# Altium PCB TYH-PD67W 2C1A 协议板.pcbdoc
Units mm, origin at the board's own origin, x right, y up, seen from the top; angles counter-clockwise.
Board outline 94.32 x 66.89 mm, 5 copper layers (Top Layer, Signal Layer 3, Signal Layer 1, Signal Layer 2, Bottom Layer), stack 0.941 mm thick; 46 components, 153 nets, 245 pads, 157 vias.
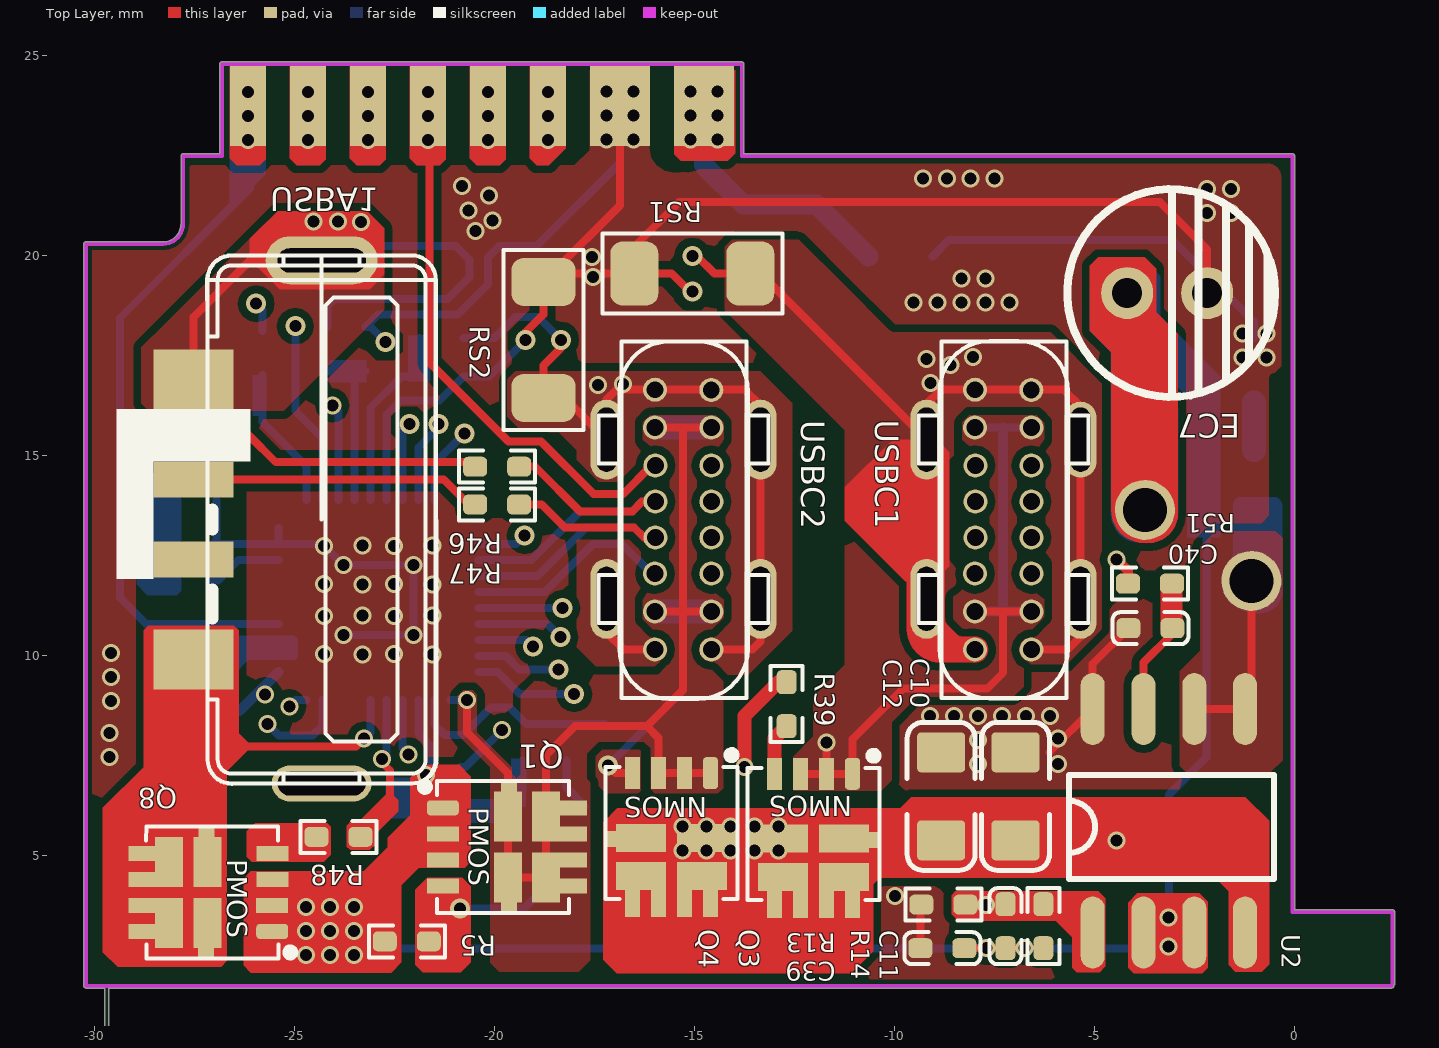
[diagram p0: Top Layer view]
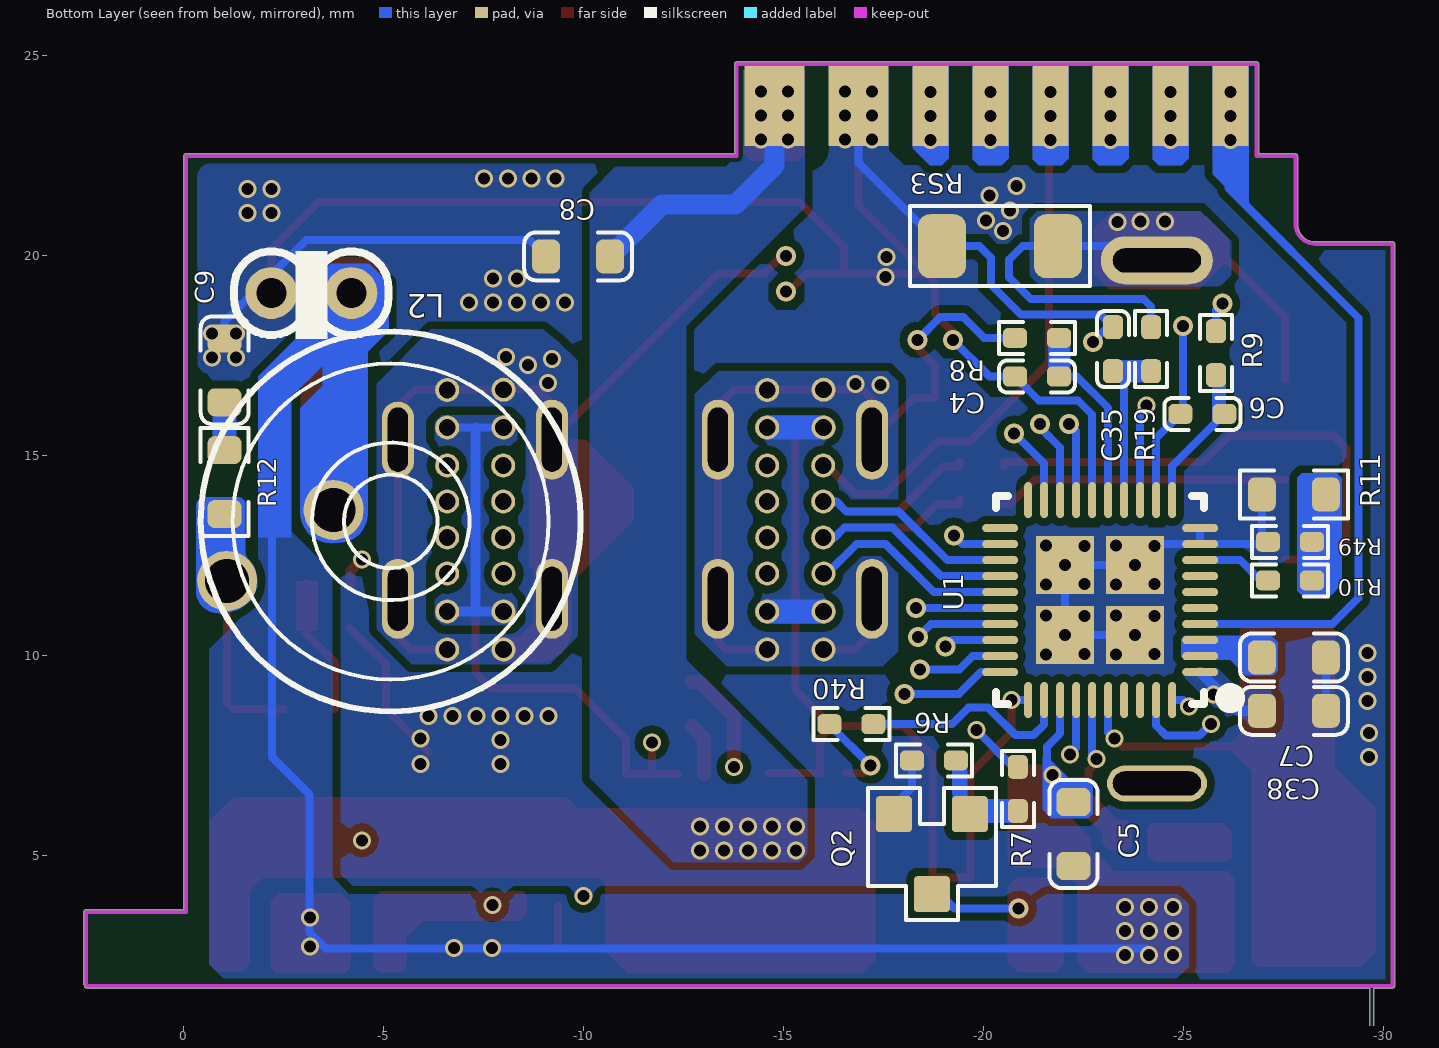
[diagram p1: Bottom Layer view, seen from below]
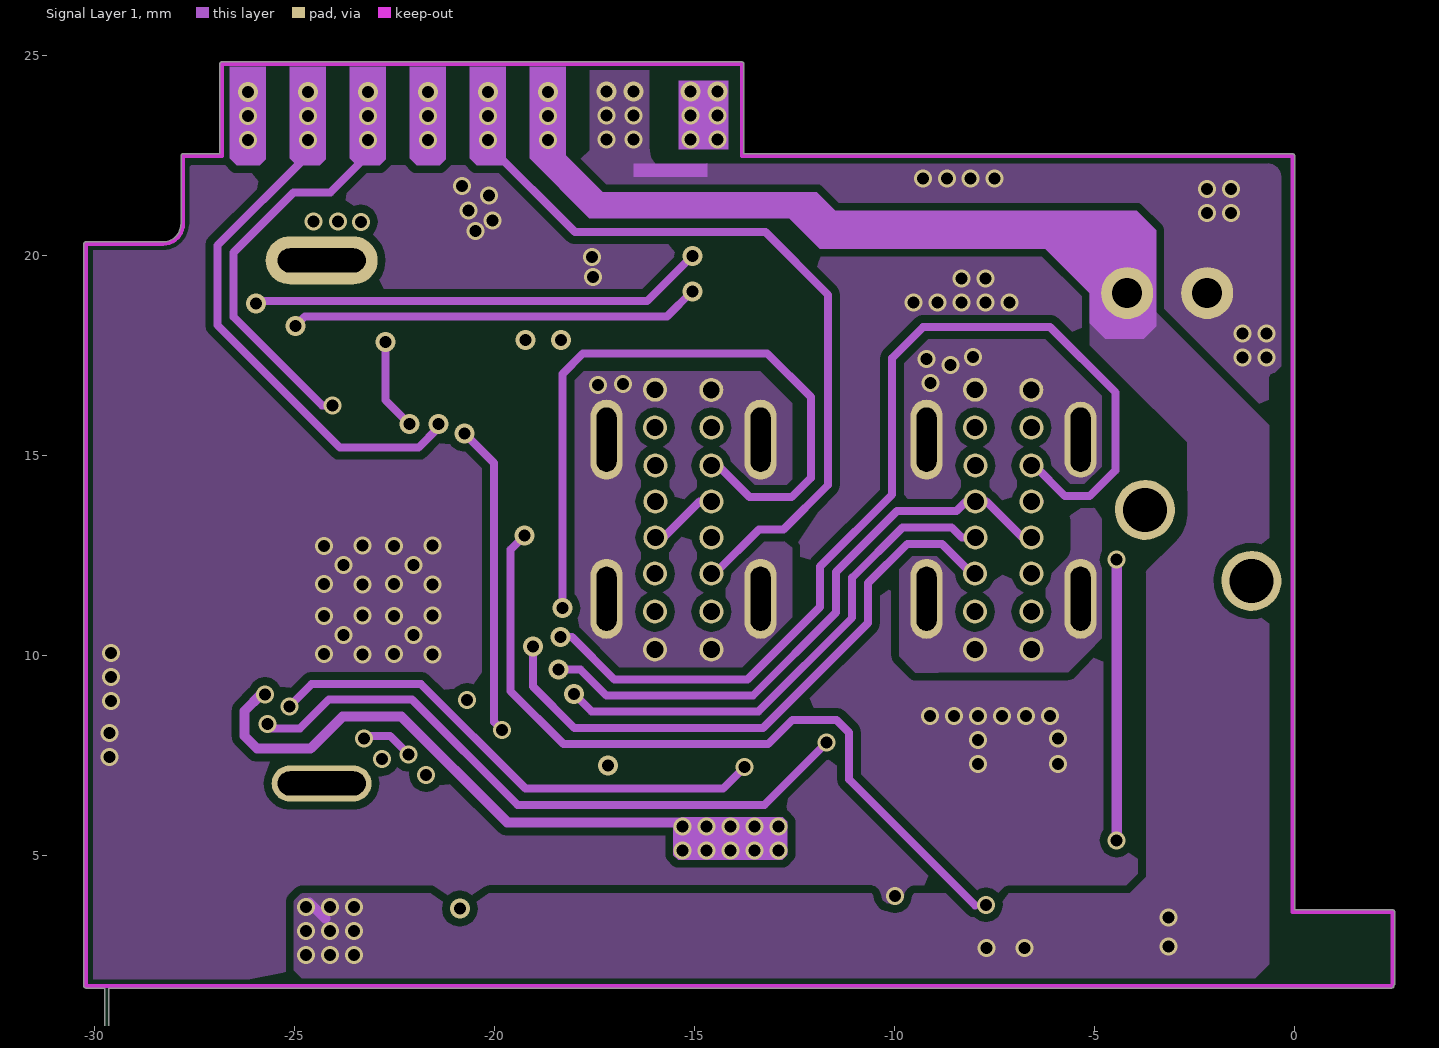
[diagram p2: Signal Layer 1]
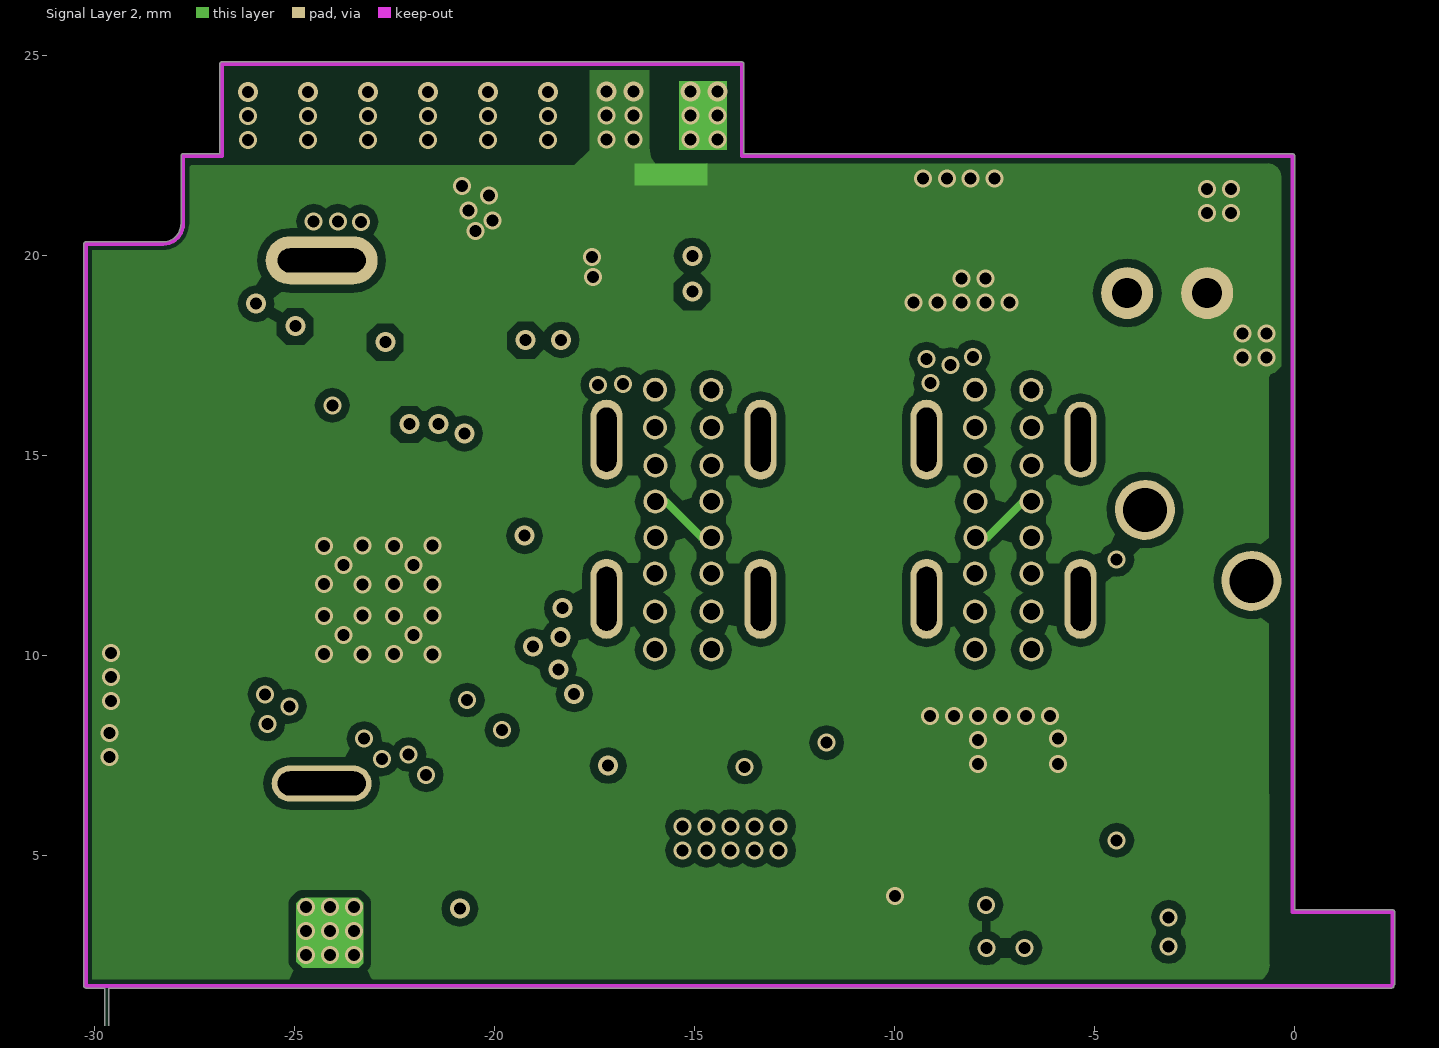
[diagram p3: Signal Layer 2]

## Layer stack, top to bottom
Top Solder: solder mask 0.0102, Solder Resist, Dk 3.5
Top Layer: signal copper 0.0356
Dielectric 1: core 0.254, FR-4, Dk 4.2
Signal Layer 3: signal copper 0.036
Dielectric 4: prepreg 0.127, Dk 4.2
Signal Layer 1: signal copper 0.036
Dielectric 2: core 0.254, Dk 4.2
Signal Layer 2: signal copper 0.036
Dielectric 3: prepreg 0.127, Dk 4.2
Bottom Layer: signal copper 0.0356
Bottom Solder: solder mask 0.0102, Solder Resist, Dk 3.5

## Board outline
-60.945,-41.225 -45.944,-41.225 ccw(c-45.944,-41.2) -45.919,-41.2 -45.919,-38.225 -43.445,-38.225 ccw(c-43.445,-38.2) -43.419,-38.2 -43.419,-37 ccw(c-43.445,-37) -43.445,-36.975 -45.919,-36.975 -45.919,-35.625 -43.445,-35.625 ccw(c-43.445,-35.6) -43.419,-35.6 -43.419,-34.4 ccw(c-43.445,-34.4) -43.445,-34.375 -45.919,-34.375 -45.919,-32.925 -43.445,-32.925 ccw(c-43.445,-32.9) -43.419,-32.9 -43.419,-27.85 -39.751,-27.85 -39.759,-40.693 ccw(c-39.709,-40.7) -39.709,-40.75 -29.759,-40.752 -29.76,-42.002 ccw(c-29.71,-42.002) -29.71,-42.052 0,-42.052 ccw(c0,-42.002) 0.05,-42.002 0.05,-37.55 2.5,-37.55 ccw(c2.5,-37.5) 2.55,-37.5 2.55,-32.55 5.163,-32.55 5.16,-37.409 ccw(c5.21,-37.409) 5.16,-37.409 ccw(c8.207,-37.409) 8.207,-40.456 ccw(c8.207,-40.406) 8.207,-40.456 ccw(c8.207,-40.406) 8.207,-40.456 25.296,-40.456 ccw(c25.296,-40.406) 25.308,-40.455 ccw(c25.296,-37.407) 28.344,-37.407 28.352,-4.393 ccw(c28.302,-4.393) 28.352,-4.393 ccw(c28.302,-4.393) 28.351,-4.381 ccw(c25.304,-4.393) 25.304,-1.346 8.229,-1.346 ccw(c8.229,-4.393) 5.181,-4.375 ccw(c5.228,-4.393) 5.178,-4.393 5.175,-9.653 ccw(c5.225,-9.653) 5.225,-9.703 6.674,-9.704 6.673,-10.703 5.225,-10.702 ccw(c5.225,-10.753) 5.174,-10.753 5.163,-32.45 0.05,-32.45 0.05,-9.32 2.5,-9.32 ccw(c2.5,-9.269) 2.55,-9.269 2.55,-2.769 ccw(c2.5,-2.769) 2.5,-2.719 0.05,-2.719 0.05,0 ccw(c0,0) 0,0.05 -29.65,0.05 -29.65,1.682 2.433,1.682 ccw(c2.433,1.733) 2.483,1.733 ccw(c2.433,1.733) 2.482,1.745 ccw(c2.45,1.784) 2.5,1.784 2.5,3.584 ccw(c2.45,3.584) 2.45,3.635 0,3.635 0,22.484 ccw(c-0.05,22.484) -0.014,22.52 ccw(c-0.05,22.484) -0.05,22.535 -13.768,22.535 -13.768,24.784 ccw(c-13.819,24.784) -13.819,24.835 -26.819,24.835 ccw(c-26.819,24.784) -26.869,24.784 -26.869,22.535 -27.789,22.535 ccw(c-27.789,22.484) -27.84,22.483 -27.84,20.784 cw(c-28.289,20.784) -28.289,20.335 cw(c-28.289,20.784) -28.289,20.335 cw(c-28.289,20.284) -28.289,20.335 -30.217,20.335 ccw(c-30.217,20.284) -30.268,20.284 -30.268,1.733 ccw(c-30.217,1.733) -30.217,1.682 -29.75,1.682 -29.75,-1.25 -31.7,-1.25 ccw(c-31.7,-1.3) -31.75,-1.3 -31.75,-26.75 -39.7,-26.75 ccw(c-39.7,-26.8) -39.75,-26.8 -39.751,-27.75 -43.445,-27.75 ccw(c-43.445,-27.8) -43.488,-27.775 -45.919,-27.775 -45.919,-24.3 ccw(c-45.945,-24.3) -45.945,-24.275 -65.945,-24.275 ccw(c-65.945,-24.3) -65.97,-24.3 -65.97,-36.2 ccw(c-60.945,-36.2)

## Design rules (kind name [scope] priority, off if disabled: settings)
Clearance Clearance_19 [InNet('NetC4_2') vs InNet('PGND')] p1: gap=0.4
Clearance Clearance_18 [InNet('NetR15_1') vs InNet('PGND')] p2: gap=1
Clearance Clearance_17 [InNet('NetN_1') vs InNet('NetBD1_1')] p3: gap=1.55
Clearance Clearance_16 [InNet('NetN_1') vs InNet('PGND')] p4: gap=1.5
Clearance Clearance_15 [InNet('VIN') vs InNet('PGND')] p5 off: gap=5.8
Clearance Clearance_14 [InNet('CS') vs InNet('Bais-L')] p6: gap=0.45
Clearance Clearance_13 [InNet('SW') vs InNet('CS')] p7: gap=1.5
Clearance Clearance_12 [InNet('NetR15_1') vs InNet('CS')] p8: gap=1
Clearance Clearance_11 [InNet('NetBD1_3') vs InNet('CS')] p9: gap=1.1
Clearance Clearance_10 [InNet('HV') vs InNet('CS')] p10: gap=1.1
Clearance Clearance_9 [InNet('NetL2_1') vs InNet('CS')] p11: gap=1.5
Clearance Clearance_8 [InNet('NetC1_2') vs InNet('PGND')] p12: gap=1.2
Clearance Clearance_7 [InNet('NetBD1_3') vs InNet('PGND')] p13: gap=1.2
Clearance Clearance_6 [InNet('NetC2_2') vs InNet('PGND')] p14: gap=1.3
Clearance Clearance_5 [InNet('Bais-L') vs InNet('PGND')] p15: gap=0.45
Clearance Clearance_4 [InNet('SW') vs InNet('PGND')] p16: gap=1.5
Clearance Clearance_3 [InNet('HV') vs InNet('PGND')] p17: gap=1.2
Clearance Clearance_2 [InNet('NetL2_1') vs InNet('PGND')] p18: gap=1.5
Clearance Clearance_1 [OnLayer('Keep-Out Layer')] p19: gap=0.1
Clearance [All] p20: gap=0.2
PlaneConnect [All] p1: planeconnectstyle=Direct reliefexpansion=0.508 reliefentries=4 reliefconductorwidth=0.3 reliefairgap=0.254
PolygonConnect [All] p1: connectstyle=Direct reliefconductorwidth=0.3 reliefentries=4 polygonreliefangle="90 Angle" airgapwidth=0.3
RoutingVias [All] p1: holewidth=0.711 width=1.27 viastyle="Through Hole" minholewidth=0.711 minwidth=1.27 maxholewidth=0.711 maxwidth=1.27
SolderMaskExpansion [All] p1: expansion=0.05
Width [All] p1: maxlimit=10 minlimit=0.1 preferedwidth=0.2
28 further rules are at their usual default settings.

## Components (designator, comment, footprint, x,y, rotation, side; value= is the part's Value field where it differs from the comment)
C4 "0.1uF" 0402C -22.279,16.568 r0 bottom
C5 "1uF" 0603CX -22.239,4.733 r90 bottom
C6 "0.1uF" 0402C -26.411,15.635 r0 bottom
C7 "1uF" 0603CX -26.947,9.945 r180 bottom
C8 "1uF" 0603CX -10.655,19.974 r0 bottom
C9 "100nF/50V/0603" 0603CX -1.018,17.925 r270 bottom
C10 "2.2nF/250V/0805" 0805C -6.977,6.474 r90 top
C11 "33nF/25V/0402" 0402C -6.826,4.177 r270 top (schematic designator C21)
C12 "100nF/50V/0603" 0805C -8.835,6.474 r90 top (schematic designator C9)
C35 "0.1uF" 0402C -22.826,16.704 r90 bottom
C38 "1uF" 0603CX -28.548,8.613 r0 bottom
C39 "33nF/25V/0402" 0402C -7.856,2.277 r180 top (schematic designator C21)
C40 "33nF/25V/0402" 0402C -4.555,11.078 r0 top (schematic designator C21)
EC7 "560uF/25V/6.3*16" EG-5*9L -4.184,19.056 r90 top (schematic designator EC6)
L2 "Comment" L-T31125W -5.169,13.346 r340 bottom
Q1 "PPM8PN03R10" DFN3*3 -18.718,5.974 r270 top
Q2 "2N7002KL SOT-23" SOT-23_R -18.699,5.028 r0 bottom (schematic designator Q8)
Q3 "PNM8PN30V50A" DFN3*3 -11.263,4.463 r180 top
Q4 "PNM8PN30V50A" DFN3*3 -14.814,4.479 r180 top
Q8 "PPM8PN03R10" DFN3*3 -28.135,3.309 r90 top
R5 "10K" 0402R#1 -22.746,2.848 r0 top (schematic designator R4)
R6 "10K" 0402R#1 -19.304,7.372 r0 bottom (schematic designator R4)
R7 "2K" 0402R#1 -20.847,7.21 r270 bottom (schematic designator R4)
R8 "100R" 0402R#1 -21.879,17.935 r0 bottom (schematic designator R4)
R9 "100R" 0402r -25.803,17.554 r270 bottom (schematic designator R4)
R10 "10K" 0402R#2 -27.654,11.872 r0 bottom (schematic designator R4)
R11 "100K" 0603Rx -26.947,14.024 r180 bottom (schematic designator R4)
R12 "10R/1206" 0603RX -1.018,15.132 r270 bottom (schematic designator R6)
R13 "1K/0402" 0402R#1 -8.231,3.767 r180 top (schematic designator R22)
R14 "1K/0402" 0402R#1 -6.281,2.677 r90 top (schematic designator R22)
R19 "100R" 0402R#1 -24.182,18.204 r270 bottom (schematic designator R4)
R39 "100R" 0402R#1 -12.698,8.229 r90 top (schematic designator R4)
R40 "100R" 0402R#1 -17.236,8.278 r0 bottom (schematic designator R4)
R46 "100R" 0402R#1 -19.386,14.714 r180 top (schematic designator R4)
R47 "100R" 0402R#1 -19.386,13.77 r180 top (schematic designator R4)
R48 "100R" 0402R#1 -24.454,5.462 r0 top (schematic designator R4)
R49 "10K" 0402R#2 -27.654,12.839 r0 bottom (schematic designator R4)
R51 "1K/0402" 0402R#1 -3.067,11.792 r180 top (schematic designator R22)
RS1 "5mR/1206/1%" 1206RA -17.257,20.543 r0 top (schematic designator RS2)
RS2 "5mR/1206" 1206RA -19.78,15.686 r90 top
RS3 "5mR/1206" 1206RA -18.2,21.227 r180 bottom (schematic designator RS2)
U1 "Comment" "QFN40 5*5" -22.907,11.38 r0 bottom
U2 "Comment" SO-8S -5.047,3.072 r0 top
USBA1 "Comment" "USB AF SMD-L" -24.325,13.396 r180 top locked
USBC1 "Comment" "USB C 16P 立式"#1 -7.266,13.387 r270 top locked
USBC2 "Comment" "USB C 16P 立式"#2 -15.267,13.387 r270 top locked

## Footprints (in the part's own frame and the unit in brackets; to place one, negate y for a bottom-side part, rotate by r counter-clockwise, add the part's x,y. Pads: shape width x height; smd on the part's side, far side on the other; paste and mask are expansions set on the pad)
0402C [mm]
  rrect50% 0.6x0.5 smd: 1(0.4,-0.4) 2(1.5,-0.4)
  silkscreen extent 0,-0.8 1.9,0, body extent 0.45,-0.66 1.45,-0.14, height 0.53
0402R#1 [mm]
  rrect50% 0.6x0.5 smd: 1(0,0) 2(1.1,0)
  silkscreen extent -0.4,-0.4 1.5,0.4, body extent 0.05,-0.25 1.05,0.25, height 0.3
0402R#2 [mm]
  rrect50% 0.6x0.5 smd: 1(-0.55,0) 2(0.55,0)
  silkscreen extent -0.95,-0.4 0.95,0.4, body extent -0.5,-0.25 0.5,0.25, height 0.3
0402r [mm]
  rrect50% 0.6x0.5 smd: 1(-0.55,0) 2(0.55,0)
  silkscreen extent -0.95,-0.4 0.95,0.4, body extent -0.5,-0.25 0.5,0.25, height 0.3
0603CX [mm]
  rrect50% 0.7x0.85 smd: 1(0,0) 2(1.6,0)
  silkscreen extent -0.55,-0.6 2.15,0.6, body extent 0,-0.41 1.6,0.41, height 0.81
0603Rx [mm]
  rrect50% 0.7x0.85 smd: 1(0,0) 2(1.6,0)
  silkscreen extent -0.55,-0.6 2.15,0.6, body extent 0.03,-0.42 1.58,0.43, height 0.45
0603RX [mm]
  rrect50% 0.7x0.85 smd: 1(0,0) 2(1.6,0)
  silkscreen extent -0.55,-0.6 2.15,0.6, body extent 0.03,-0.42 1.58,0.43, height 0.45
0805C [mm]
  rrect20% 1x1.2 smd: 1(-1.099,0.001) 2(1.101,0.001)
  silkscreen extent -1.85,-0.85 1.85,0.85, body extent -1,-0.61 1,0.61, height 0.51
1206RA [mm]
  rrect50% 1.2x1.6 smd mask+0.03: 1(3.65,-1) 2(0.75,-1)
  silkscreen extent -0.05,-2 4.45,0, body extent 0.6,-1.8 3.8,-0.2, height 0.55
DFN3*3 [mm]
  rrect50% 0.38x0.8 smd: 1(-0.212,-2.576)
  rect 0.38x0.8 smd: 2(0.438,-2.576) 3(1.088,-2.576) 4(1.738,-2.576)
  rect 0.38x1 smd: 5(1.738,0.524) 6(1.088,0.524) 7(0.438,0.524) 8(-0.212,0.524)
  rect 0.8x0.4 smd: 8(-0.458,-0.926) 8(2.034,-0.926)
  rect 1.25x0.7 smd: 8(0,-0.952) 8(0,0) 8(1.526,-0.952) 8(1.526,0)
  silkscreen extent -0.89,-3.18 2.41,0.57, body extent -0.89,-2.74 2.41,0.58, height 0.75
EG-5*9L [mm]
  round 1.3 hole 0.75: 1(0,0) 2(0,-2)
  silkscreen extent -2.6,-3.7 2.6,1.5, body extent -2.49,-3.49 2.51,1.51, height 9.02
L-T31125W [mm]
  round 1.5 hole 1.1: 1(1.241,-0.758) 2(4.35,0)
  silkscreen extent -4.75,-4.75 4.75,4.75, body extent -4.77,-4.77 4.77,4.77, height 4.86
"QFN40 5*5" [mm]
  oval 0.9x0.2 smd: 1(-2.5,1.8) 2(-2.5,1.4) 3(-2.5,1) 4(-2.5,0.6) 5(-2.5,0.2) 6(-2.5,-0.2) 7(-2.5,-0.6) 8(-2.5,-1) 9(-2.5,-1.4) 10(-2.5,-1.8) 21(2.5,-1.8) 22(2.5,-1.4) 23(2.5,-1) 24(2.5,-0.6) 25(2.5,-0.2) 26(2.5,0.2) 27(2.5,0.6) 28(2.5,1) 29(2.5,1.4) 30(2.5,1.8)
  oval 0.2x0.9 smd: 11(-1.8,-2.5) 12(-1.4,-2.5) 13(-1,-2.5) 14(-0.6,-2.5) 15(-0.2,-2.5) 16(0.2,-2.5) 17(0.6,-2.5) 18(1,-2.5) 19(1.4,-2.5) 20(1.8,-2.5) 31(1.8,2.5) 32(1.4,2.5) 33(1,2.5) 34(0.6,2.5) 35(0.2,2.5) 36(-0.2,2.5) 37(-0.6,2.5) 38(-1,2.5) 39(-1.4,2.5) 40(-1.8,2.5)
  rect 1.45x1.45 smd: 41(-0.875,-0.875) 41(-0.875,0.875) 41(0.875,-0.875) 41(0.875,0.875)
  silkscreen extent -3.37,-2.6 2.6,2.6, body extent -2.45,-2.45 2.45,2.45, height 0.8
SO-8S [mm]
  oval 0.6x1.8 smd: 1(0,0) 2(1.27,0) 3(2.54,0) 4(3.81,0) 5(3.81,5.588) 6(2.54,5.588) 7(1.27,5.588) 8(0,5.588)
  silkscreen extent -0.59,1.34 4.54,3.94, body extent -0.59,-0.26 4.41,5.74, height 1.9
SOT-23_R [mm]
  rrect20% 0.9x0.9 smd: 1(-0.95,-1) 2(0.95,-1) 3(0,1)
  silkscreen extent -1.6,-1.65 1.6,1.65, body extent -1.46,-1.44 1.44,1.36, height 1.2
"USB AF SMD-L" [mm]
  oval 2.5x0.9 hole 0.6 slot 2.2 at 0 deg: 0(0,6.6)
  oval 2.8x1.2 hole 0.6 slot 2.2 at 0 deg: 0(0,-6.475)
  rect 2x1.5 smd: +(3.198,3.5) -(3.198,-3.5)
  rect 2x0.9 smd: D+P(3.198,-1) D-M(3.198,1)
  silkscreen extent -2.85,-6.6 2.85,6.6, body extent -2.9,-6.61 3.42,6.61, height 10
"USB C 16P 立式"#1 [mm]
  round 0.6 hole 0.42: CC1(-1.355,0.685) CC2(1.345,-0.725) DM(-0.455,-0.715) DM(0.445,0.685) DP(-0.455,0.685) DP(0.445,-0.715) GND(-3.253,-0.723) GND(-3.247,0.684) GND(3.245,-0.725) GND(3.245,0.685) SBU1(1.345,0.685) SBU2(-1.355,-0.715) VBUS(-2.305,-0.725) VBUS(-2.305,0.685) VBUS(2.295,-0.725) VBUS(2.295,0.685)
  oval 2x0.8 hole 0.5 slot 1.6 at 0 deg: GND(-2.005,-1.935) GND(1.975,1.915) GND(1.975,-1.935)
  oval 1.9x0.8 hole 0.5 slot 1.6 at 0 deg: GND(-2.005,1.915)
  silkscreen extent -4.45,-2.13 4.46,2.12, body extent -4.47,-2.08 4.47,2.08, height 10
"USB C 16P 立式"#2 [mm]
  round 0.6 hole 0.42: CC1(-1.355,0.685) CC2(1.345,-0.725) DM(-0.455,-0.715) DM(0.445,0.685) DP(-0.455,0.685) DP(0.445,-0.715) GND(-3.253,-0.723) GND(-3.247,0.684) GND(3.245,-0.725) GND(3.245,0.685) SBU1(1.345,0.685) SBU2(-1.355,-0.715) VBUS(-2.305,-0.725) VBUS(-2.305,0.685) VBUS(2.295,-0.725) VBUS(2.295,0.685)
  oval 2x0.8 hole 0.5 slot 1.6 at 0 deg: GND(-2.005,-1.935) GND(-2.005,1.915) GND(1.975,1.915) GND(1.975,-1.935)
  silkscreen extent -4.45,-2.13 4.46,2.12, body extent -4.47,-2.08 4.47,2.08, height 10

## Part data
C9 C12: library part "Cap Semi", "Capacitor (Semiconductor SIM Model)"
C10: library part CAP
C11 C39 C40: library part Cap, "Capacitor"
EC7: library part CAPACITOR, "C?"
Q2: library part NMOS
R5 R6 R7 R8 R9 R10 R11 R19 R39 R40 R46 R47 R48 R49 RS1 RS2 RS3: library part RES, "Resistor"
R12 R13 R14 R51: library part Res1, "Resistor"

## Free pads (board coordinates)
  rect 1.5x2 smd far side: 0(-16.869,23.734) 1(-14.769,23.734)
  rect 1.5x2 smd: 0(-16.869,23.734) 1(-14.769,23.734)
  rect 0.9x2 smd far side: 2(-26.169,23.734) 2(-24.669,23.734) 2(-23.169,23.734) 2(-21.669,23.734) 2(-20.169,23.734) 2(-18.669,23.734)
  rect 0.9x2 smd: 2(-26.169,23.734) 2(-24.669,23.734) 2(-23.169,23.734) 2(-21.669,23.734) 2(-20.169,23.734) 2(-18.669,23.734)

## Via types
v1: diameter 0.45, hole 0.3, Top Layer to Bottom Layer, tented both sides, 129 vias
v2: diameter 0.5, hole 0.3, Top Layer to Bottom Layer, tented both sides, 28 vias

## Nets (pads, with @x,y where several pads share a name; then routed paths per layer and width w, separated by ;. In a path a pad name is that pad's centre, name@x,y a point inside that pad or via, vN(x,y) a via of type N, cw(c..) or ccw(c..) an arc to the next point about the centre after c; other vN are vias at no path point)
3.3V: 
A: 
A+: Q8.5 Q8.6 Q8.7 Q8.8 U1.34 U1.36 USBA1.+ | length 17.2
  Top Layer w0.2: -28.572,4.835 -28.572,3.309 -27.62,3.309 -27.524,3.405 -27.524,7.718 ; USBA1.+ -27.524,7.718 ; v1(-23.263,7.917) -23.462,7.718 -27.524,7.718
  Signal Layer 1 w0.2: v1(-23.263,7.917) -23.199,7.981 -22.609,7.981 v1(-22.148,7.52)
  Bottom Layer w0.2: v1(-23.263,7.917) -23.107,8.073 U1.36 ; U1.34 -22.307,7.679 v1(-22.148,7.52)
A-: R19.1 RS3.1 USBA1.0@-24.325,19.871 USBA1.- | length 14.1
  Top Layer w0.2: USBA1.- -27.524,18.46 -26.112,19.871 USBA1.0@-24.325,19.871
  Bottom Layer w0.2: USBA1.0@-24.325,19.871 -23.97,20.227 RS3.1 -20.965,20.227 -20.629,19.891 -20.629,19.449 -21.177,18.901 -23.995,18.901 -24.182,18.714 R19.1
  other v1: -24.522,20.85 -23.918,20.85 -23.346,20.837
Bais-L: 
BOOT0: 
CC1: 
CC2: 
CPA: C35.1 R19.2 U1.14 | length 4.3
  Bottom Layer w0.2: R19.2 C35.1 -23.507,16.823 U1.14
CS: 
D: 
D+: R47.2 USBA1.D+P | length 7.3
  Top Layer w0.2: USBA1.D+P -21.273,14.396 -20.647,13.77 R47.2
D-: R46.2 USBA1.D-M | length 13.2
  Top Layer w0.2: USBA1.D-M -28.652,12.396 -29.066,12.81 -29.066,15.164 -28.736,15.494 -26.138,15.494 -25.471,14.827 R46.2@-20.599,14.827 ; R46.2@-20.504,14.836 -20.513,14.827 R46.2@-20.599,14.827 ; R46.2 R46.2@-20.599,14.827
DM: 
DP: 
EM: 
EN: C40.2 R51.1 U2.7 | length 3.4
  Top Layer w0.2: U2.7 -3.777,9.817 -3.067,10.527 R51.1
EN_IC: 
FB: 
G-SR: 
GND-C: 
HV: 
ISET: 
KEY: 
KEY1: 
LEDA: 
M: 
N: 
NetBD1_1: 
NetBD1_3: 
NetBD2_1: 
NetC1_2: 
NetC2_2: 
NetC3_2: 
NetC4_1: 
NetC4_2: 
NetC6_1: 
NetC10_2: 
NetC21_1: 
NetC22_1: C9.2 R12.1 | length 1.2
  Bottom Layer w0.6: R12.1 C9.2
NetC24_1: 
NetC25_2: 
NetC26_2: 
NetC30_2: 
NetC31_2: 
NetC100_2: 
NetC101_1: 
NetC101_2: 
NetC112_1: 
NetD4_K: 
NetF1_1: 
NetF1_2: 
NetKEY1_1: 
NetL2_1: 
NetLF1_2: 
NetN_1: 
NetNTC2_1: 
NetQ1_3: 
NetQ3_4: 
NetR15_1: 
NetR25_2: 
NetR29_1: 
NetR31_2: 
NetR32_2: 
NetR41_2: 
NetR42_2: 
NetR134_1: 
NetRX1_2: 
NetRX3_2: 
NetU1_26: 
NetU1_27: 
NetU1_28: 
NetU1_29: 
NetU1_30: 
NetU1_32: 
NewNet1: U1.25 USBC2.CC2 | length 5.2
  Bottom Layer w0.2: U1.25 -18.746,11.58 -17.543,12.784 -16.822,12.784 -16.081,12.042 USBC2.CC2
NewNet2: Q1.5 Q1.6 Q1.7 Q1.8 Q4.1 Q4.2 Q4.3 U1.31 USBC2.VBUS | length 28.2
  Top Layer w0.2: v1(-20.685,8.88) -20.685,8.069 -19.67,7.055 -19.67,5.974 -19.67,4.448 -18.718,4.448 -18.718,5.974 -18.718,7.501 -17.993,8.226 -16.192,8.226 ; USBC2.VBUS@-15.991,11.092 -15.286,11.092 ; USBC2.VBUS@-15.991,15.692 USBC2.VBUS@-14.581,15.692 ; -15.286,15.674 -15.286,11.092 ; Q4.1 Q4.3 -15.902,7.936 -16.192,8.226 ; USBC2.VBUS@-14.581,11.092 -15.286,11.092 ; -16.192,8.226 -15.286,9.132 -15.286,11.092
  Bottom Layer w0.2: U1.31 v1(-20.685,8.88)
  Bottom Layer w0.6: USBC2.VBUS@-15.991,11.092 USBC2.VBUS@-14.581,11.092 ; USBC2.VBUS@-15.991,15.692 USBC2.VBUS@-14.581,15.692
NewNet3: R47.1 U1.24 USBC2.DP | length 10.8
  Top Layer w0.2: R47.1@-19.404,13.892 R47.1@-19.386,13.892 ; R47.1 -18.823,13.77 -18.244,13.191 -16.51,13.191 -16.261,12.942 USBC2.DP@-15.981,12.942
  Signal Layer 1 w0.2: USBC2.DP@-15.981,12.942 -15.775,12.942 -14.875,13.842 USBC2.DP@-14.581,13.842
  Bottom Layer w0.2: U1.24 -18.926,11.98 -17.716,13.191 -16.51,13.191 -16.261,12.942 USBC2.DP@-15.981,12.942 ; USBC2.DP@-14.581,13.842 USBC2.DP@-14.364,13.842
NewNet4: R46.1 U1.23 USBC2.DM | length 10.8
  Top Layer w0.2: R46.1@-19.404,14.836 R46.1@-19.386,14.836 ; R46.1 -18.984,14.714 -17.866,13.596 -16.558,13.596 -16.312,13.842 USBC2.DM@-15.981,13.842
  Signal Layer 2 w0.2: USBC2.DM@-15.981,13.842 -15.722,13.842 -14.822,12.942 USBC2.DM@-14.581,12.942
  Bottom Layer w0.2: U1.23 -19.084,12.38 -17.868,13.596 -16.558,13.596 -16.312,13.842 USBC2.DM@-15.981,13.842
NewNet5: U1.26 USBC2.CC1 | length 19.9
  Signal Layer 1 w0.2: v2(-18.304,11.18) -18.304,17.036 -17.789,17.551 -13.187,17.551 -12.092,16.455 -12.092,14.437 -12.573,13.956 -13.627,13.956 -14.413,14.742 USBC2.CC1
  Bottom Layer w0.2: U1.26 v2(-18.304,11.18)
NewNet6: Q4.4 R40.1 R40.2 U1.32 | length 7.6
  Top Layer w0.2: v2(-17.161,7.243) -16.973,7.055 Q4.4
  Bottom Layer w0.2: U1.32 -21.507,8.273 -21.239,8.005 -20.788,8.005 -20.102,8.691 -19.617,8.691 -19.205,8.278 R40.1 ; v2(-17.161,7.243) -16.136,8.269 R40.2
NewNet7: 
NewNet8: U1.27 USBC1.CC1 | length 28
  Signal Layer 1 w0.2: v2(-18.356,10.455) -18.067,10.455 -17.007,9.395 -13.681,9.395 -11.864,11.211 -11.864,12.217 -10.065,14.016 -10.065,17.426 -9.286,18.206 -6.112,18.206 -4.48,16.574 -4.48,14.626 -5.128,13.978 -5.739,13.978 -6.503,14.742 USBC1.CC1
  Bottom Layer w0.2: U1.27 -18.681,10.78 v2(-18.356,10.455)
NewNet9: U1.29 USBC1.DM | length 17.2
  Signal Layer 1 w0.2: v2@-18.48,9.604 v2@-18.465,9.589 ; v2(-18.408,9.646) -17.857,9.646 -17.201,8.99 -13.546,8.99 -11.465,11.072 -11.465,12.081 -9.938,13.608 -8.45,13.608 -8.215,13.842 -7.706,13.842 -6.806,12.942 USBC1.DM@-6.581,12.942
  Bottom Layer w0.2: U1.29 -19.719,9.98 -19.384,9.646 v2(-18.408,9.646)
NewNet10: U1.30 USBC1.DP | length 17.4
  Signal Layer 1 w0.2: v2(-18.011,9.032) -17.572,8.593 -13.408,8.593 -11.061,10.94 -11.061,11.94 -9.806,13.195 -8.574,13.195 -8.32,12.942 USBC1.DP@-7.981,12.942 ; USBC1.DP@-6.581,13.842 USBC1.DP@-6.372,13.842
  Signal Layer 2 w0.2: USBC1.DP@-7.981,12.942 -7.683,12.942 -6.783,13.842 USBC1.DP@-6.581,13.842
  Bottom Layer w0.2: U1.30 -19.921,9.58 -19.372,9.032 v2(-18.011,9.032)
NewNet11: U1.28 USBC1.CC2 | length 16.8
  Signal Layer 1 w0.2: v2(-19.039,10.214) -19.039,9.216 -18.007,8.185 -13.286,8.185 -10.662,10.81 -10.662,11.805 -9.683,12.783 -8.819,12.783 -8.078,12.042 USBC1.CC2
  Signal Layer 2 w0.2: USBC1.CC2@-8.056,12.042 USBC1.CC2
  Bottom Layer w0.2: U1.28 -19.205,10.38 v2(-19.039,10.214)
NewNet12: 
NewNet13: Q1.4 Q2.3 R5.2 | length 4.4
  Top Layer w0.2: R5.2 -21.294,3.2 -21.294,3.687 ; Q1.4 -21.294,3.687 ; v2(-20.869,3.669) -20.887,3.687 -21.294,3.687
  Bottom Layer w0.2: v2(-20.869,3.669) -19.267,3.669 Q2.3@-18.698,4.238
NewNet14: 
NewNet15: 
NewNet16: 
NewNet18: Q2.1 R6.1 R7.2 | length 2.5
  Bottom Layer w0.2: R7.2 -19.776,6.11 -19.648,6.238 -19.304,6.582 R6.1
NewNet22: 
NewNet23: 
NewNet24: R8.2 RS2.2 USBC2.GND | length 21.1
  Top Layer w0.2: v2(-18.337,17.886) -18.337,17.684 -18.78,17.242 RS2.2 -18.246,16.436 -17.201,15.392 -17.201,16.394 -16.956,16.64 -15.99,16.64 -13.748,16.64 -13.351,16.243 -13.351,15.392 -13.351,10.349 -13.558,10.142 USBC2.GND@-14.581,10.142 ; USBC2.GND@-17.201,11.412 -17.201,10.573 -16.77,10.142 USBC2.GND@-15.991,10.142
  Bottom Layer w0.2: R8.2 -20.006,17.935 -19.488,18.453 -18.905,18.453 v2(-18.337,17.886)
  other v1: -17.417,16.761 -16.79,16.785
NewNet25: C4.1 R8.1 U1.15 | length 4.8
  Bottom Layer w0.2: U1.15 -23.107,16.188 -22.322,16.972 -21.879,16.972 R8.1
NewNet28: Q3.4 R39.1 R39.2 U1.40 | length 17.4
  Top Layer w0.35: v1(-13.748,7.207) -13.748,8.485 -12.904,9.329 R39.2 ; Q3.4 -13.001,7.926 R39.1
  Signal Layer 1 w0.2: v1(-25.131,8.726) -24.574,9.282 -21.845,9.282 -19.231,6.669 -14.286,6.669 v1(-13.748,7.207)
  Bottom Layer w0.2: v1(-25.131,8.726) -24.976,8.88 U1.40
NewNet32: R10.1 R11.2 R49.1 | length 2.3
  Bottom Layer w0.2: R11.2 -28.204,13.682 R10.1
NewNet33: pad.2@-26.169,23.734 U1.4 | length 17.9
  Bottom Layer w0.2: pad.2@-26.169,23.734 -26.169,21.731 -26.118,21.68 -29.36,18.438 -29.36,11.43 -28.71,10.78 U1.4
  other v1: -26.166,22.883 -26.166,23.482
  other v2: -26.166,24.081
NewNet34: C7.1 U1.2 U1.3 | length 1.9
  Bottom Layer w0.2: C7.1@-26.911,9.98 U1.2 U1.3
NewNet36: C6.1 R9.2 U1.11 | length 3.6
  Bottom Layer w0.2: R9.2 -25.803,15.828 -24.707,14.731 U1.11
NewNet38: R7.1 U1.19 | length 11.2
  Signal Layer 1 w0.2: v2(-20.756,15.545) -20.018,14.808 -20.018,8.338 v1(-19.81,8.13)
  Bottom Layer w0.2: U1.19 -21.507,14.795 v2(-20.756,15.545) ; R7.1 -20.729,7.21 v1(-19.81,8.13)
NewNet40: 
NewNet41: Q3.1 Q3.2 Q3.3 U1.39 USBC1.VBUS | length 36
  Top Layer w0.2: Q3.3 Q3.1 -11.051,7.901 -9.787,9.166 -7.684,9.166 -7.286,9.564 -7.286,11.092 ; Q3.2 v1(-11.701,7.815) ; USBC1.VBUS@-7.991,11.092 -7.286,11.092 ; USBC1.VBUS@-6.581,11.092 -7.286,11.092
  Signal Layer 1 w0.2: v1(-25.676,8.282) -25.568,8.174 -24.868,8.174 -24.146,8.896 -22.063,8.896 -19.43,6.262 -13.255,6.262 v1(-11.701,7.815)
  Bottom Layer w0.2: v1(-25.676,8.282) -25.391,7.997 -24.55,7.997 -24.307,8.24 U1.39 ; USBC1.VBUS@-7.991,15.692 -7.286,15.692 USBC1.VBUS@-6.581,15.692
  Bottom Layer w0.25: USBC1.VBUS@-7.991,11.092 -7.286,11.092 ; -7.286,15.692 -7.286,11.092 ; USBC1.VBUS@-6.581,11.092 -7.286,11.092
NewNet42: R9.1 RS1.1 USBC1.GND | length 34.3
  Top Layer w0.2: v2(-15.057,19.985) -14.947,19.985 -14.504,19.543 RS1.1 -13.353,19.543 -9.201,15.392 -9.201,16.279 -8.841,16.64 -7.99,16.64 -5.771,16.64 -5.351,16.219 -5.351,15.392 -5.351,10.464 -5.673,10.142 USBC1.GND@-6.581,10.142 ; USBC1.GND@-9.201,11.412 -9.201,10.662 -8.681,10.142 USBC1.GND@-7.991,10.142
  Signal Layer 1 w0.2: v2(-25.964,18.79) -25.897,18.857 -16.185,18.857 v2(-15.057,19.985)
  Bottom Layer w0.2: v2(-25.964,18.79) -25.803,18.629 R9.1
  other v1: -9.099,16.806 -8.603,17.263 -9.202,17.404 -8.046,17.454
OPTO: 
OTP: R10.2 U1.8 | length 1.9
  Bottom Layer w0.2: R10.2 -26.916,11.872 -26.408,12.38 U1.8
PA2: 
PA4: 
PA5: 
PA6: 
PA7: 
PA8: 
PA9: 
PB0: 
PB1: 
PF0: 
PF1: 
PF3: 
PGND: 
RS: 
RST: 
SCL: pad.2@-24.669,23.734 U1.18 | length 14.8
  Signal Layer 1 w0.2: v1(-24.666,22.883) -24.666,22.509 -26.933,20.242 -26.933,18.257 -23.865,15.189 -21.905,15.189 -21.4,15.695 v2(-21.4,15.782)
  Bottom Layer w0.2: U1.18 -21.907,15.189 -21.4,15.696 v2(-21.4,15.782)
  other v1: -24.666,23.482
  other v2: -24.666,24.081
SCL1: 
SDA: pad.2@-23.169,23.734 U1.13 | length 12.2
  Signal Layer 1 w0.2: v1(-24.059,16.25) -24.317,16.25 -26.529,18.462 -26.529,20.072 -25.031,21.57 -24.107,21.57 -23.166,22.511 v1(-23.166,22.883)
  Bottom Layer w0.2: v1(-24.059,16.25) -23.907,16.098 U1.13
  other v1: -23.166,23.482
  other v2: -23.166,24.081
SDA1: 
SET: 
SGND: C4.2 C5.1 C6.2 C7.2 C8.2 C9.1 C10.2 C12.2 C35.2 C38.1 C39.2 C40.1 EC7.2 pad.0 Q2.2 R6.2 R11.1 R13.2 R49.2 RS1.2 RS2.1 RS3.2 U1.9 U1.10 U1.12 U1.16 U1.17 U1.41 U2.8 | length 91.2
  Top Layer w0.2: v2(-19.222,17.886) -19.222,18.084 -18.78,18.526 RS2.1 RS2.1@-18.572,19.543 ; pad.0@-16.869,23.734 -16.869,21.247 RS2.1@-18.572,19.543 ; v2(-15.057,19.101) -15.131,19.101 -15.573,19.543 RS1.2 ; C39.2 R13.2@-9.356,3.742 ; -6.132,7.575 U2.8 -5.047,9.787 C40.1 ; EC7.2 -2.184,20.144 -3.368,21.328 -15.393,21.328 -16.507,20.214 RS1.2 ; RS2.1@-18.572,19.543 RS1.2
  Signal Layer 1 w0.2: v2(-24.982,18.23) -24.746,18.467 -15.691,18.467 v2(-15.057,19.101) ; v2(-22.73,17.838) -22.73,16.377 v2(-22.132,15.779)
  Bottom Layer w0.2: C38.1@-28.547,8.614 C7.2 ; R11.1 -26.947,12.879 -27.046,12.78 U1.9 ; U1.10 U1.9 ; v2(-24.982,18.23) -24.982,16.106 C6.2 -24.307,15.43 U1.12 ; v1(-23.782,10.505) v1(-22.032,10.505) v1(-22.032,12.255) v1(-23.782,12.255) -24.307,12.78 U1.9 ; v2(-22.73,17.838) -23.096,18.204 C35.2 -22.912,18.518 -20.923,18.518 -20.171,19.27 -20.171,19.948 -19.892,20.227 RS3.2 -16.869,22.308 pad.0@-16.869,23.734 ; U1.16 -22.707,16.016 -22.358,16.365 -21.382,16.365 C4.2 -20.14,16.968 v2(-19.222,17.886) ; U1.17 -22.307,15.605 v2(-22.132,15.779) ; R6.2 -18.204,6.693 Q2.2@-17.748,6.238 ; C8.2 -8.646,20.383 -3.06,20.383 -1.018,18.341 C9.1
  other v1: -9.993,3.986 -7.916,7.277 -5.909,7.277 -29.627,7.463 -7.916,7.877 -5.909,7.915 -29.627,8.063 -9.116,8.477 -8.516,8.477 -7.916,8.477 -7.316,8.477 -6.716,8.477 -6.116,8.477 -29.585,8.854 -29.585,9.454 -24.263,10.033 -23.306,10.02 -22.513,10.033 -21.556,10.02 -29.585,10.054 -24.263,10.978 -23.306,10.991 -22.513,10.978 -21.556,10.991 -24.263,11.783 -23.306,11.77 -22.513,11.783 -21.556,11.77 -24.263,12.728 -22.513,12.728 -23.306,12.741 -21.556,12.741 -1.308,17.45 -0.708,17.45 -1.308,18.05 -0.708,18.05 -9.528,18.822 -8.928,18.822 -8.328,18.822 -7.728,18.822 -7.128,18.822 -8.328,19.422 -7.728,19.422 -17.536,19.454 -17.562,19.953 -20.481,20.603 -20.048,20.868 -2.192,21.058 -1.592,21.058 -20.649,21.123 -20.141,21.496 -2.192,21.658 -1.592,21.658 -20.817,21.727 -9.288,21.924 -8.688,21.924 -8.099,21.924 -7.499,21.924 -17.207,22.892 -16.531,22.892 -17.207,23.49 -16.531,23.49
  other v2: -17.207,24.089 -16.531,24.089
SRCG_A: Q8.4 R48.1 R48.2 U1.35 | length 5.1
  Top Layer w0.2: Q8.4 -24.869,5.047 R48.1 ; R48.2 -22.611,6.205 -22.611,7.114 -22.81,7.312 v1(-22.81,7.409)
  Bottom Layer w0.2: v1(-22.81,7.409) -22.707,7.512 U1.35
SW: 
SW-SR: L2.2 R12.2 U2.5 U2.6 | length 6.1
  Top Layer w0.2: U2.6 U2.5 -1.081,8.816 L2.2
  Bottom Layer w0.2: L2.2@-1.018,11.922 R12.2
SWCLK: 
SWCLK1: 
SWCLK2: pad.2@-21.669,23.734 USBC2.SBU2 | length 12.9
  Top Layer w0.2: pad.2@-21.626,22.883 -21.626,17.318 -19.655,15.346 -18.837,15.346 -17.522,14.032 -16.786,14.032 -16.076,14.742 USBC2.SBU2
  other v1: -21.666,22.883 -21.666,23.482
  other v2: -21.666,24.081
SWDIO: 
SWDIO1: 
SWDIO2: pad.2@-20.169,23.734 USBC2.SBU1 | length 18.8
  Signal Layer 1 w0.2: v1(-20.166,22.883) -20.166,22.752 -17.994,20.58 -13.231,20.58 -11.661,19.01 -11.661,14.262 -12.775,13.148 -13.392,13.148 -14.498,12.042 USBC2.SBU1
  other v1: -20.166,23.482
  other v2: -20.166,24.081
SWRST: 
TXD: 
U2-2: 
V3V3: 
VBUS: 
VC: 
VDD: 
VDD1: 
VDS: 
VFB: 
VFB1: C11.1 R13.1 R14.2 U1.22 U2.1 | length 23.7
  Top Layer w0.3: R13.1@-8.231,3.755 -5.731,3.755 U2.1
  Signal Layer 1 w0.2: v2(-19.252,12.989) -19.602,12.639 -19.602,9.103 -18.28,7.781 -13.159,7.781 -12.558,8.382 -11.456,8.382 -11.14,8.067 -11.14,6.899 -7.992,3.75
  Bottom Layer w0.2: U1.22 -19.461,12.78 v2(-19.252,12.989)
  other v1: -7.717,3.762
VIN: C8.1 C10.1 C12.1 C38.2 pad.1 Q3.5 Q3.6 Q3.7 Q3.8 Q4.5 Q4.6 Q4.7 Q4.8 R51.2 U1.1 U2.4 | length 51.3
  Top Layer w0.254: Q4.8@-16.34,5.431 -16.34,4.479 -14.814,4.479 Q4.8@-14.814,5.431 ; v1(-14.701,5.721) Q3.8@-12.692,5.721 ; Q3.8@-12.789,5.415 -12.789,4.463 -11.263,4.463 Q3.8@-11.263,5.375 ; Q3.8@-11.223,5.375 C10.1 -2.128,5.375 -1.237,4.484 U2.4 ; v1(-4.447,12.392) -4.167,12.111 R51.2
  Signal Layer 1 w0.254: v1(-25.739,9.026) -25.831,9.026 -26.251,8.606 -26.251,7.984 -25.939,7.672 -24.6,7.672 -23.8,8.471 -22.335,8.471 -19.686,5.823 -15.206,5.823 -14.814,5.431 ; v1(-4.447,5.375) v1(-4.447,12.392)
  Bottom Layer w0.254: C38.2 -26.374,8.613 U1.1
  Bottom Layer w0.5: pad.1@-14.769,23.734 -14.769,22.254 -13.78,21.265 -11.947,21.265 C8.1
  other v1: -15.301,5.121 -14.701,5.121 -14.101,5.121 -13.501,5.121 -12.901,5.121 -15.301,5.721 -14.101,5.721 -13.501,5.721 -12.901,5.721 -15.107,22.892 -14.431,22.892 -15.107,23.49 -14.431,23.49
  other v2: -15.107,24.089 -14.431,24.089
VMS: 
VOUT1: C5.2 C11.2 C39.1 EC7.1 L2.1 pad.2@-18.669,23.734 Q1.1 Q1.2 Q1.3 Q8.1 Q8.2 Q8.3 R5.1 R14.1 U1.33 U2.2 U2.3 | length 61.6
  Top Layer w0.2: -22.063,5.701 -21.578,6.186 Q1.1 ; C39.1 v1@-6.748,2.677
  Top Layer w0.25: -25.996,4.397 -25.996,3.097 -25.747,2.848 R5.1 -22.746,4.503 -22.363,4.886 Q1.3 Q1.1 ; U2.2 U2.3
  Signal Layer 1 w0.254: v1@-24.626,3.812 -24.235,3.421 ; v1(-18.666,22.883) -18.666,22.452 -17.443,21.229
  Bottom Layer w0.2: v1@-24.074,2.675 -3.539,2.675 -3.142,3.072 -3.142,6.517 -2.199,7.459 -2.199,17.071 EC7.1 -4.184,14.076 L2.1 ; U1.33 -21.907,8.043 -21.578,7.715 -21.578,7.141 v1(-21.711,7.008)
  other v1: -24.721,2.51 -24.121,2.51 -23.521,2.51 -7.7,2.679 -6.748,2.687 -3.149,2.717 -24.721,3.11 -24.121,3.11 -23.521,3.11 -3.149,3.45 -24.721,3.71 -24.121,3.71 -23.521,3.71 -18.666,23.482
  other v2: -18.666,24.081
VXO: 
XGND: 
pads on no net: U1.5 U1.6 U1.7 U1.20 U1.21 U1.37 U1.38 USBA1.0@-24.325,6.796 USBC1.SBU1 USBC1.SBU2

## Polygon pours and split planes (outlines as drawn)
NewNet2 on Bottom Layer "Bottom Layer-No Net" (solid, remove dead copper, pour order 111): -15.991,16.202 -14.425,16.202 -14.11,15.887 -14.11,10.842 -14.221,10.731 -16.297,10.731 -16.462,10.897 -16.462,15.887 -16.187,16.163
SGND on Bottom Layer "Bottom Layer-No Net" (solid, remove dead copper, pour order 109): -17.624,24.732 -17.624,22.631 -18.005,22.25 -18.797,22.25 -27.589,22.25 -27.789,22.049 -27.789,21.614 cw(c-28.289,21.614) -28.289,21.114 -30.2,21.114 -30.2,1.784 -1.125,1.784 ccw(c-1.125,2.275) -0.635,2.275 -0.635,16.933 cw(c-0.509,16.933) -0.509,17.059 ccw(c-0.509,17.228) -0.34,17.228 -0.34,17.44 -0.34,21.961 ccw(c-0.67,21.961) -0.67,22.291 -14.68,22.291 ccw(c-14.68,22.165) -14.769,22.254 cw(c-15.191,22.676) -15.191,22.079 -15.349,22.079 -15.51,22.079 cw(c-15.51,22.697) -16.128,22.697 -16.128,24.729 -17.237,24.729
NewNet24 on Bottom Layer "Bottom Layer-No Net" (solid, remove dead copper, pour order 110): -13.359,17.107 -17.599,17.107 -17.854,16.852 -17.854,10.102 -17.474,9.723 -13.575,9.723 -12.919,10.379 -12.777,10.521 -12.777,10.731 -12.777,16.525 -13.359,17.107
VOUT1 on Bottom Layer "Bottom Layer-No Net" (solid, remove dead copper, pour order 79): -1.856,11.374 -0.635,10.153 -0.635,2.275 -0.986,1.924 -24.816,1.924 -25.12,2.229 -25.12,3.761 -24.849,4.032 -4.139,4.032 -3.712,4.458 -3.712,12.07 -2.684,13.098 -2.684,16.46 -2.17,16.974 -1.856,16.974
VIN on Bottom Layer "Bottom Layer-No Net" (solid, remove dead copper, pour order 105): -15.515,24.736 -15.515,21.184 -12.558,18.227 -12.558,9.89 -15.577,6.87 -15.577,5.023 -15.382,4.827 -12.251,4.827 -10.144,6.934 -10.144,21.57 -10.788,22.214 -13.548,22.214 -13.819,22.484 -13.819,24.784 -15.499,24.784 -15.518,24.765
NewNet41 on Bottom Layer "Bottom Layer-No Net" (solid, remove dead copper, pour order 83): -8.131,16.007 -6.449,16.007 -6.267,15.826 -6.267,10.946 -6.426,10.787 -6.467,10.746 -6.691,10.746 -8.18,10.746 -8.329,10.895 -8.329,15.81 -8.131,16.007
NewNet42 on Bottom Layer "Bottom Layer-No Net" (solid, remove dead copper, pour order 84): -8.97,18.15 -6.176,18.15 -4.821,16.795 -4.821,10.654 -5.701,9.774 -9.144,9.774 -9.511,10.141 -9.887,10.517 -9.887,10.897 -9.887,17.317 -9.346,17.857
A- on Bottom Layer "Bottom Layer-No Net" (solid, remove dead copper, pour order 90): -25.67,20.863 -25.426,21.107 -23.144,21.107 -21.334,21.107 -21.147,20.92 -21.147,19.489 -21.412,19.224 -25.907,19.224 -26.183,19.499 -26.183,20.35 -25.67,20.863
VIN on Bottom Layer "Bottom Layer-No Net" (solid, remove dead copper, pour order 96): -27.278,8.153 -26.302,8.153 -25.487,8.968 -24.956,9.498 -24.956,9.597 -25.041,9.681 -25.098,9.681 -25.838,9.681 -26.09,9.429 -26.38,9.14 -26.874,9.14 -27.165,9.14 -27.376,8.928 -27.376,8.258 -27.295,8.177
SGND on Top Layer "Bottom Layer-No Net" (solid, remove dead copper, pour order 108): -17.624,24.732 -17.624,22.631 -18.005,22.25 -18.797,22.25 -27.589,22.25 -27.789,22.049 -27.789,21.614 cw(c-28.289,21.614) -28.289,21.114 -30.2,21.114 -30.2,1.784 -1.125,1.784 ccw(c-1.125,2.275) -0.635,2.275 -0.635,16.933 cw(c-0.509,16.933) -0.509,17.059 ccw(c-0.509,17.228) -0.34,17.228 -0.34,17.44 -0.34,21.961 ccw(c-0.67,21.961) -0.67,22.291 -14.68,22.291 ccw(c-14.68,22.165) -14.769,22.254 cw(c-15.191,22.676) -15.191,22.079 -15.349,22.079 -15.51,22.079 cw(c-15.51,22.697) -16.128,22.697 -16.128,24.729 -17.237,24.729
NewNet41 on Top Layer "Bottom Layer-No Net" (solid, remove dead copper, pour order 64): -12.465,6.615 -10.788,6.615 -10.331,6.615 -10.074,6.873 -10.074,8.329 -9.598,8.805 -9.445,8.957 -8.168,8.957 -7.033,8.957 -6.772,9.218 -6.772,9.831 -6.836,9.896 -6.874,9.933 -6.874,10.14 -6.874,10.34 -6.335,10.878 -6.264,10.95 -6.264,11.065 -6.264,15.822 -6.409,15.967 -6.449,16.007 -6.554,16.007 -8.131,16.007 -8.312,15.826 -8.312,14.911 -9.08,14.144 -9.836,14.144 -11.241,12.738 -11.241,9.757 -12.029,8.97 -12.029,7.975 -12.539,7.465 -12.539,6.637 -12.522,6.62
NewNet2 on Top Layer "Bottom Layer-No Net" (solid, remove dead copper, pour order 69): -19.884,2.092 -17.894,2.092 -17.604,2.382 -17.604,6.819 -17.703,6.917 -17.703,7.533 -17.393,7.843 -16.268,7.843 -16.097,7.672 -16.097,6.649 -16,6.552 -14.416,6.552 -14.286,6.682 -14.286,9.35 -14.885,9.949 -14.885,10.331 -14.273,10.943 -14.273,15.814 -14.456,15.997 -16.12,15.997 -16.298,15.819 -16.298,10.905 -15.703,10.31 -15.703,9.726 -15.91,9.519 -18.835,9.519 -19.347,9.008 -19.347,7.025 -19.452,6.92 -19.567,7.036 -19.567,7.2 -20.442,8.075 -20.442,9.011 -20.552,9.12 -20.789,9.12 -20.92,8.989 -20.92,8.01 -20.11,7.199 -20.11,2.318
A- on Top Layer "Bottom Layer-No Net" (solid, remove dead copper, pour order 70): -28.564,16.111 -25.266,16.111 -24.494,16.883 -22.754,18.623 -22.754,19.447 -22.754,20.409 -23.208,20.863 -25.67,20.863 -28.238,18.295 -28.829,17.704 -28.829,17.131 -28.829,16.297 -28.692,16.16
NewNet24 on Top Layer "Bottom Layer-No Net" (solid, remove dead copper, pour order 72): -19.476,17.107 -13.359,17.107 -12.558,16.306 -12.558,10.618 -13.656,9.519 -17.27,9.519 -17.949,10.198 -17.949,15.128 -18.4,15.579 -19.385,15.579 -19.687,15.882 -19.687,16.896
NewNet6 on Top Layer "Bottom Layer-No Net" (solid, remove dead copper, pour order 75): -17.393,7.843 -16.584,7.843 -16.352,7.611 -16.352,6.615 -16.402,6.565 -16.416,6.551 -16.438,6.551 -17.212,6.551 -17.38,6.719 -17.466,6.805 -17.466,7.082 -17.466,7.769 -17.393,7.843
SW-SR on Top Layer "Bottom Layer-No Net" (solid, remove dead copper, pour order 86): -2.712,7.071 -0.611,7.071 -0.3,7.382 -0.3,12.933 -0.47,13.103 -1.987,13.103 -2.363,12.728 -2.363,10.112 -2.877,9.598 -2.877,7.236
NewNet42 on Top Layer "Bottom Layer-No Net" (solid, remove dead copper, pour order 68): -14.063,20.392 -12.396,20.392 -10.127,18.123 -10.02,18.078 -6.104,18.078 -4.821,16.795 -4.821,10.654 -5.701,9.774 -9.34,9.774 -11.241,11.675 -11.241,15.622 -14.249,18.629 -14.249,20.207
SGND on Signal Layer 1 "Bottom Layer-No Net" (solid, remove dead copper, pour order 107): -17.624,24.732 -17.624,22.631 -18.005,22.25 -18.797,22.25 -27.589,22.25 -27.789,22.049 -27.789,21.614 cw(c-28.289,21.614) -28.289,21.114 -30.2,21.114 -30.2,1.784 -1.125,1.784 ccw(c-1.125,2.275) -0.635,2.275 -0.635,16.933 cw(c-0.509,16.933) -0.509,17.059 ccw(c-0.509,17.228) -0.34,17.228 -0.34,17.44 -0.34,21.961 ccw(c-0.67,21.961) -0.67,22.291 -14.68,22.291 ccw(c-14.68,22.165) -14.769,22.254 cw(c-15.191,22.676) -15.191,22.079 -15.349,22.079 -15.51,22.079 cw(c-15.51,22.697) -16.128,22.697 -16.128,24.729 -17.237,24.729
NewNet24 on Signal Layer 1 "Bottom Layer-No Net" (solid, remove dead copper, pour order 76): -17.937,11.441 -17.937,10.603 -17.032,9.698 -16.853,9.519 -14.167,9.519 -13.656,9.519 -12.726,10.449 -12.558,10.618 -12.558,10.865 -12.558,16.306 -13.359,17.107 -17.773,17.107 -18.077,16.802 -18.077,11.607 -17.949,11.479
NewNet42 on Signal Layer 1 "Bottom Layer-No Net" (solid, remove dead copper, pour order 77): -8.903,9.571 -5.654,9.571 -4.821,10.429 -4.821,16.751 -6.318,18.292 -7.003,18.292 -9.015,18.292 -9.887,17.395 -9.887,9.974 -9.574,9.653 -9.488,9.564 -8.851,9.564
VOUT1 on Signal Layer 1 "Bottom Layer-No Net" (solid, remove dead copper, pour order 87): -5.121,19.734 -5.121,17.757 -4.357,16.993 -2.684,15.32 -2.684,14.705 -2.684,13.516 cw(c-3.625,13.516) -2.96,12.851 -3.692,12.118 ccw(c-3.645,12.07) -3.712,12.07 -3.712,4.458 -4.123,4.048 -24.833,4.048 -25.023,3.858 -25.023,2.131 -24.816,1.924 -0.986,1.924 -0.635,2.275 -0.635,15.753 -3.187,18.305 -3.602,18.72 -3.602,19.803 -3.747,19.948 -4.907,19.948 -5.121,19.734
SGND on Signal Layer 2 "Bottom Layer-No Net" (solid, remove dead copper, pour order 106): -17.624,24.732 -17.624,22.631 -18.005,22.25 -18.797,22.25 -27.589,22.25 -27.789,22.049 -27.789,21.614 cw(c-28.289,21.614) -28.289,21.114 -30.2,21.114 -30.2,1.784 -1.125,1.784 ccw(c-1.125,2.275) -0.635,2.275 -0.635,16.933 cw(c-0.509,16.933) -0.509,17.059 ccw(c-0.509,17.228) -0.34,17.228 -0.34,17.44 -0.34,21.961 ccw(c-0.67,21.961) -0.67,22.291 -14.68,22.291 ccw(c-14.68,22.165) -14.769,22.254 cw(c-15.191,22.676) -15.191,22.079 -15.349,22.079 -15.51,22.079 cw(c-15.51,22.697) -16.128,22.697 -16.128,24.729 -17.237,24.729

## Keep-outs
Keep-Out Layer:
  lines w0.1: -0.05,22.484 -0.05,3.584 2.45,3.584 2.45,1.784 ; 2.433,1.733 -30.217,1.733 -30.217,20.284 -28.289,20.284 ccw(c-28.289,20.784) -27.789,20.784 -27.789,22.484 -26.819,22.484 -26.819,24.784 -13.819,24.784 -13.819,22.484 ; -13.819,22.484 -0.05,22.484 -13.819,22.484

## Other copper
Top Layer:
  rectangle net EN: -3.353,10.618 -2.804,11.854
  region net VIN: -15.515,24.622 -15.515,22.527 -15.348,22.361 -14.176,22.361 -13.981,22.555 -13.981,24.622
  region net NewNet42: -9.729,11.847 -11.241,13.359 -11.241,14.196 -10.045,15.392 -8.945,15.392 -8.633,15.08 -8.633,12.226 -9.082,11.777 -9.152,11.847
  region net NewNet33: -26.621,24.716 -26.621,22.421 -26.45,22.25 -25.874,22.25 -25.719,22.404 -25.719,24.716
  region net SCL: -25.121,24.716 -25.121,22.421 -24.95,22.25 -24.374,22.25 -24.219,22.404 -24.219,24.716
  region net SDA: -23.621,24.716 -23.621,22.421 -23.45,22.25 -22.874,22.25 -22.719,22.404 -22.719,24.716
  region net SWCLK2: -22.121,24.716 -22.121,22.421 -21.95,22.25 -21.374,22.25 -21.219,22.404 -21.219,24.716
  region net SWDIO2: -20.621,24.716 -20.621,22.421 -20.45,22.25 -19.874,22.25 -19.719,22.404 -19.719,24.716
  region net VOUT1: -19.121,24.716 -19.121,22.421 -18.95,22.25 -18.644,22.25 -18.219,22.675 -18.219,24.716
  region net A+: -28.654,10.742 -26.519,10.742 -26.399,10.622 -26.399,8.055 -26.072,7.728 -26.519,7.281 -26.519,7.278 -26.692,7.105 -26.692,2.358 -26.838,2.212 -29.427,2.212 -29.793,2.578 -29.793,6.184 -28.771,7.206 -28.771,10.625
  region net VOUT1: -26.096,4.601 -23.274,4.601 -22.667,5.207 -22.667,5.435 -21.541,6.561 -20.811,6.561 -20.595,6.345 -20.595,4.839 -20.75,4.684 -21.901,4.684 -22.329,4.256 -22.329,2.326 -22.585,2.069 -26.1,2.069 -26.277,2.246 -26.277,4.42
  region net SRCG_A: -26.075,4.842 -24.266,4.842 -24.095,5.012 -24.095,5.715 -24.183,5.803 -25.99,5.803 -26.195,5.597 -26.195,4.962
  region net SRCG_A: -22.629,6.596 -23.353,5.871 -23.575,5.871 -23.701,5.745 -23.701,5.219 -23.615,5.133 -23.117,5.133 -22.977,5.273 -22.977,5.538 -22.414,6.101 -22.414,6.381
  region net NewNet13: -21.796,2.075 -20.845,2.075 -20.595,2.325 -20.595,4.224 -20.809,4.438 -21.685,4.438 -21.983,4.14 -21.983,2.262
  region net VIN: -16.943,2.053 -11.089,2.053 -10.535,2.607 -10.535,4.272 -10.37,4.436 -1.985,4.436 -1.647,4.099 -1.647,2.261 -1.478,2.092 -0.818,2.092 -0.638,2.272 -0.638,5.859 -1.229,6.449 -9.585,6.449 -9.861,6.173 -16.929,6.173 -17.286,5.817 -17.286,2.395
  region net VOUT1: -3.932,4.045 -2.381,4.045 -2.17,3.835 -2.17,2.195 -2.308,2.057 -4.027,2.057 -4.164,2.193 -4.164,3.814
  region net A-: -25.426,21.107 -23.18,21.107 -22.754,20.681 -22.754,19.529 -23.127,19.155 -25.376,19.155 -26.124,19.904 -26.124,20.409
  region net VOUT1: -20.595,6.965 -20.889,7.259 -21.787,7.259 -22.109,6.936 -22.109,5.747 -22.063,5.701 -20.673,5.701 -20.595,5.779
  pour cut-out: -19.132,18.632 -19.132,18.959 -18.555,18.959 -18.468,18.871 -18.468,18.38 -18.77,18.078 -18.77,17.646 -18.999,17.416 -19.448,17.416 -19.682,17.65 -19.682,18.082
  pour cut-out: -15.809,19.211 -16.147,19.211 -16.147,19.86 -15.452,19.86 -15.143,19.552 -14.864,19.552 -14.605,19.293 -14.605,18.844 -14.839,18.61 -15.209,18.61
  pour cut-out: -28.975,9.354 -28.583,8.962 -26.735,8.962 -26.195,9.502 -26.195,14.155 -26.266,14.226 -26.581,13.91 -28.975,13.91
  region net VFB1: -4.903,4.099 -4.729,3.924 -4.729,2.221 -4.875,2.075 -5.443,2.075 -5.56,2.191 -5.56,2.953 -5.966,3.359 -8.411,3.359 -8.576,3.524 -8.576,4.002 -8.479,4.099
  region net NewNet42: -9.361,12.464 -8.911,12.464 -8.744,12.297 -8.744,10.82 -8.386,10.462 -7.976,10.462 cw(c-7.976,10.153) -7.667,10.153 -7.667,10.141 cw(c-7.987,10.141) -7.987,9.821 -8.851,9.821 cw(c-8.851,10.661) -9.691,10.661 -9.691,12.133 cw(c-9.364,12.133) -9.364,12.459
  region net VOUT1: -3.758,12.808 cw(c-3.758,13.637) -4.588,13.637 -4.588,17.58 -5.121,18.113 -5.121,19.734 -4.907,19.948 -3.747,19.948 -3.457,19.658 -3.457,18.575 -2.917,18.035 -2.917,13.548 cw(c-3.655,13.548) -3.655,12.811
Signal Layer 1:
  rectangle net VIN: -15.404,22.646 -14.148,24.368
  rectangle net SGND: -16.525,21.962 -14.68,22.301
  region net VOUT1: -18.219,24.716 -18.219,22.504 -17.291,21.576 -11.942,21.576 -11.479,21.112 -3.948,21.112 -3.457,20.621 -3.457,18.228 -3.772,17.913 -4.729,17.913 -5.121,18.305 -5.121,19.057 -6.233,20.169 -11.877,20.169 -12.638,20.929 -17.629,20.929 -19.121,22.421 -19.121,24.716
  region net VOUT1: -19.121,24.716 -19.121,22.421 -18.95,22.25 -18.644,22.25 -18.219,22.675 -18.219,24.716
  region net SWDIO2: -20.621,24.716 -20.621,22.421 -20.45,22.25 -19.719,22.25 -19.719,24.716
  region net SWCLK2: -22.121,24.716 -22.121,22.421 -21.95,22.25 -21.374,22.25 -21.219,22.404 -21.219,24.716
  region net SDA: -23.621,24.716 -23.621,22.421 -23.45,22.25 -22.874,22.25 -22.719,22.404 -22.719,24.716
  region net NewNet33: -26.621,24.716 -26.621,22.421 -26.45,22.25 -25.874,22.25 -25.719,22.404 -25.719,24.716
  region net SCL: -25.121,24.716 -25.121,22.421 -24.95,22.25 -24.374,22.25 -24.219,22.404 -24.219,24.716
  pour cut-out: -25.117,18.756 -16.058,18.756 -15.262,19.552 -14.864,19.552 -14.605,19.293 -14.605,18.861 -14.834,18.631 -15.059,18.631 -15.536,18.154 -24.366,18.154 -24.759,17.761 -25.208,17.761 -25.442,17.995 -25.442,18.431
  pour cut-out: -23.19,18.034 -23.19,17.603 -23.073,17.486 -23.073,16.236 -22.596,15.759 -22.593,15.759 -22.593,15.544 -22.358,15.309 -21.91,15.309 -21.68,15.539 -21.68,15.971 -21.939,16.23 -22.138,16.23 -22.418,16.509 -22.418,17.459 -22.278,17.598 -22.278,18.031 -22.537,18.289 -22.935,18.289
  region net VIN: -15.331,5.952 -12.792,5.952 -12.678,5.838 -12.678,5.018 -12.809,4.887 -15.411,4.887 -15.528,5.004 -15.528,5.838 -15.441,5.926
Signal Layer 2:
  rectangle net SGND: -16.508,21.748 -14.68,22.301
  rectangle net VIN: -15.388,22.639 -14.189,24.363
  region net VOUT1: -24.736,3.941 -23.41,3.941 -23.288,3.819 -23.288,2.297 -23.401,2.183 -24.799,2.183 -24.956,2.34 -24.956,3.803 -24.83,3.929
Bottom Layer:
  rectangle net NewNet36: -26.05,15.98 -25.716,17.009
  rectangle net CPA: -24.123,16.817 -23.203,17.378
  rectangle net NewNet25: -22.165,16.845 -21.601,17.99
  rectangle net NewNet18: -20.794,5.811 -19.529,6.411
  rectangle net NewNet18: -19.589,6.204 -19.211,7.422
  region net VOUT1: -19.121,24.716 -19.121,22.421 -18.95,22.25 -18.644,22.25 -18.219,22.675 -18.219,24.716
  region net SWDIO2: -20.621,24.716 -20.621,22.421 -20.45,22.25 -19.874,22.25 -19.719,22.404 -19.719,24.716
  region net SWCLK2: -22.121,24.716 -22.121,22.421 -21.95,22.25 -21.374,22.25 -21.219,22.404 -21.219,24.716
  region net SDA: -23.621,24.716 -23.621,22.421 -23.45,22.25 -22.874,22.25 -22.719,22.404 -22.719,24.716
  region net SCL: -25.121,24.716 -25.121,22.421 -24.95,22.25 -24.374,22.25 -24.219,22.404 -24.219,24.716
  region net NewNet33: -26.622,24.727 -26.622,21.241 -26.567,21.187 -26.56,21.187 -25.717,22.029 -25.717,24.727
  region net VOUT1: -22.604,5.929 -21.688,5.929 -21.474,6.143 -21.474,7.461 -21.583,7.569 -21.583,7.463 -22.109,6.936 -22.512,6.936 -22.718,6.731 -22.718,6.044
  pour cut-out: -19.534,20.537 -20.09,20.537 -20.512,20.115 -20.512,19.392 -21.062,18.841 -23.612,18.841 -23.787,18.667 -23.787,17.716 -23.592,17.521 -23.081,17.521 -22.944,17.384 -22.436,17.384 -22.275,17.545 -22.275,18.086 -22.134,18.227 -20.756,18.227 -19.848,19.136 -19.848,19.799 -19.758,19.888 -19.503,19.888 -19.4,19.991 -19.4,20.461 -19.467,20.528
  pour cut-out: -24.492,13.19 -24.138,13.19 -24.009,13.319 -24.009,15.695 -24.313,16 -24.313,16.472 -24.62,16.779 -24.62,17.757 -24.515,17.862 -24.515,18.478 -24.726,18.689 -25.184,18.689 -25.441,18.433 -25.441,18.04 -25.306,17.906 -25.306,16.552 -25.506,16.352 -25.506,15.752 -25.249,15.494 -24.816,15.494 -24.607,15.285 -24.607,13.305
  pour cut-out: -22.868,13.183 -22.133,13.183 -22.004,13.312 -22.004,15.243 -21.649,15.599 -21.649,15.899 -21.51,16.038 -21.242,16.038 -20.833,16.447 -20.176,16.447 -19.237,17.386 -19.237,17.409 -19.025,17.409 -18.77,17.664 -18.77,18.078 -19.029,18.337 -19.443,18.337 -19.706,18.074 -19.706,17.837 -20.075,17.468 -21.214,17.468 -21.325,17.357 -21.325,16.837 -21.492,16.669 -22.488,16.669 -23.006,16.152 -23.006,13.321
  region net NewNet32: -28.827,14.549 -27.945,14.549 -27.836,14.44 -27.836,11.618 -27.947,11.506 -28.686,11.506 -28.95,11.771 -28.95,14.426
  region net NewNet34: -27.187,10.486 -25.008,10.486 -24.928,10.405 -24.928,9.957 -25.002,9.883 -26.156,9.883 -26.536,9.502 -27.236,9.502 -27.341,9.608 -27.341,10.331
  region net VOUT1: -3.866,12.815 cw(c-3.866,13.54) -4.591,13.54 -4.591,17.583 -5.121,18.113 -5.121,19.306 -4.633,19.795 -3.668,19.795 -3.355,19.481 -3.355,18.473 -1.856,16.974 -1.856,12.951 -2.684,12.951 -2.684,16.46 -3.466,17.242 -3.466,16.737 -2.908,16.178 -2.908,13.578 cw(c-3.68,13.578) -3.68,12.806 -3.706,12.806
  region net SW-SR: -1.285,13.957 -0.522,13.957 cw(c-0.522,13.742) -0.306,13.742 -0.306,11.608 cw(c-0.863,11.608) -0.863,11.051 -0.949,11.051 cw(c-0.949,12.008) -1.625,11.332 -1.628,11.334 cw(c-1.124,11.838) -1.836,11.838 -1.836,11.861 cw(c-1.066,11.861) -1.611,12.406 ccw(c-1.796,12.591) -1.534,12.591 -1.534,13.78 cw(c-1.361,13.78) -1.361,13.952
Multi-Layer:
  pour cut-out: -19.427,18.337 -19.029,18.337 -18.77,18.078 -18.77,17.646 -18.999,17.416 -19.448,17.416 -19.682,17.65 -19.682,18.082
  pour cut-out: -22.338,16.23 -21.939,16.23 -21.68,15.971 -21.68,15.539 -21.91,15.309 -22.358,15.309 -22.593,15.544 -22.593,15.975
  pour cut-out: -22.935,18.289 -22.537,18.289 -22.278,18.031 -22.278,17.598 -22.507,17.369 -22.956,17.369 -23.19,17.603 -23.19,18.034
  pour cut-out: -25.187,18.681 -24.789,18.681 -24.53,18.423 -24.53,17.99 -24.759,17.761 -25.208,17.761 -25.442,17.995 -25.442,18.426
  pour cut-out: -15.262,19.552 -14.864,19.552 -14.605,19.293 -14.605,18.861 -14.834,18.631 -15.283,18.631 -15.517,18.865 -15.517,19.297

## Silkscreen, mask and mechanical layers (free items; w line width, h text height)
Top Overlay:
  rectangle: -29.453,11.911 -28.531,16.154
  rectangle: -29.453,14.839 -26.102,16.154
  lines w0.1: -26.563,6.785 cw(c-26.565,7.395) -27.175,7.396 -27.175,18.33 -27.187,19.385 ; -26.563,6.796 -22.063,6.796 ccw(c-22.051,7.396) -21.452,7.396 -21.463,19.396 ; -24.325,13.396 -24.325,19.996 ; -22.063,19.996 -26.563,19.996 ccw(c-26.562,19.371) -27.187,19.385 ; -21.463,19.385 -27.187,19.385 ; -16.876,10.16 ccw(c-15.626,10.159) -15.627,8.909 -14.917,8.909 ccw(c-14.916,10.159) -13.666,10.158 -13.662,16.598 ccw(c-14.912,16.599) -14.912,17.849 -15.622,17.849 ccw(c-15.622,16.599) -16.872,16.6 -16.876,10.16 ; -8.876,10.168 ccw(c-7.626,10.167) -7.627,8.917 -6.917,8.917 ccw(c-6.916,10.167) -5.666,10.166 -5.662,16.606 ccw(c-6.912,16.607) -6.911,17.857 -7.621,17.857 ccw(c-7.622,16.607) -8.872,16.608 -8.876,10.168
  text "NMOS" at -11.054,6.472 h0.5 r180
  text "NMOS" at -14.682,6.449 h0.5 r180
  text "PMOS" at -20.65,6.198 h0.5 r270
  text "PMOS" at -26.68,4.905 h0.5 r270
